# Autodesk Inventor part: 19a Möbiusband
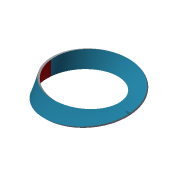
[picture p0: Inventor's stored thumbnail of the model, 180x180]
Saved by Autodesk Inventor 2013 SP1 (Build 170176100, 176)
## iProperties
Created: 2012-10
Part Number: 19a Möbiusband
Material: Allgemein
Document SubType Name: Modeling
Designer: Administrator
Density: 1 g/cm^3
Mass: 125.623 g
Surface Area: 568.268 cm^2
Volume: 125.623 cm^3
Author: Administrator
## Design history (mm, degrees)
sketch "3D-Skizze1"
  node "3D-Gleichungskurve1" dims "d0" = 0, "d1" = 1800
sketch "3D-Skizze2"
  node "3D-Gleichungskurve2" dims "d2" = 0, "d3" = 1800
node "Mittelachse Band"
  node "3D-Gleichungskurve3" dims "d17" = 0, "d18" = 3600
workplane "Arbeitsebene31"
sketch "Skizze6"
  geometry: L1 (20, -2.5)-(-20, -2.5); L2 (-20, -2.5)-(-20, 2.5); L3 (-20, 2.5)-(20, 2.5); L4 (20, 2.5)-(20, -2.5); L5 (20, -2.5)-(-20, 2.5); L6 (-20, -2.5)-(20, 2.5); 3 further points
  constraints: 12 end point, 3 midpoint, 2 parallel, 1 horizontal, 1 perpendicular
  dimensions: "d29" = 5 distance between parallel lines of L1 L3
feature "Sweeping2" sketch "Skizze6" dims "d31" = 0
sketch "3D-Skizze9"
sketch "3D-Skizze10"
sketch "Skizze7"
  geometry: 6 further points
  constraints: 3 horizontal alignment, 2 vertical alignment
feature "Sweeping3" sketch "3D-Skizze9", "3D-Skizze10", "Skizze7" dims "d36" = 0
node "Volumenkörper2"
node "3D-Gleichungskurve5" dims "d32" = 1800, "d33" = 3600
node "3D-Gleichungskurve6" dims "d34" = 1800, "d35" = 3600
